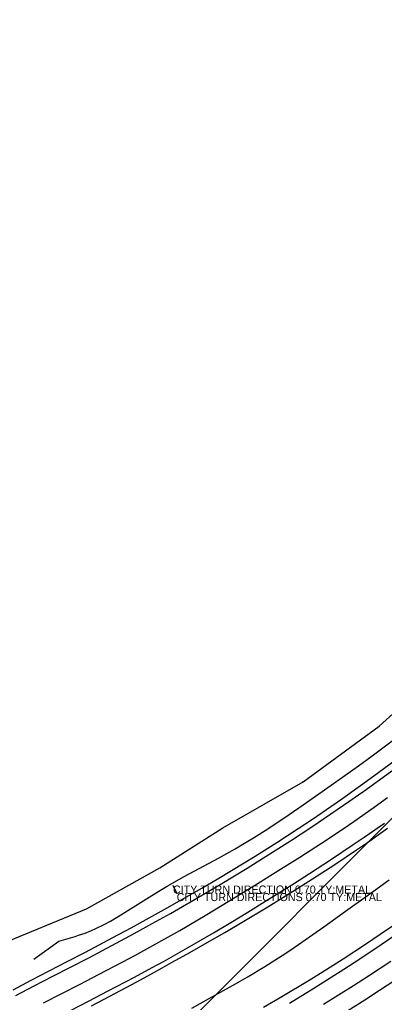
# Model space of a CAD drawing. Extents: x 1676038 to 1677961, y 226475 to 233854.
# Drawn here: x 1676549 to 1676777, y 227687 to 228301 of the extents above; entities that cross this region are included whole.
import ezdxf

# ---------------------------------------------------------------- set-up
doc = ezdxf.new("R2010")
doc.units = 0
for name, color, linetype in [('S_BASELINE', 7, 'Continuous'), ('S_DITCHLINE', 7, 'Continuous'), ('S_EDGE_PAVEMENT', 7, 'Continuous'), ('S_FIBER_OPTIC_CABLE', 7, 'Continuous'), ('S_MSC_PT_SYM', 7, 'Continuous'), ('S_PAVEMENT_CROWN', 7, 'Continuous'), ('S_SHOULDER', 7, 'Continuous'), ('S_SIGN', 7, 'Continuous'), ('S_SIGN_ANNOT', 7, 'Continuous'), ('S_UTL_PT_SYM', 7, 'Continuous')]:
    doc.layers.add(name, color=color, linetype=linetype)

msp = doc.modelspace()

# ---------------------------------------------------------------- linework, layer by layer
at = {"layer": 'S_BASELINE'}
msp.add_line((1676625.89, 227646.73), (1677368.16, 228389.18), dxfattribs=at)
at = {"layer": 'S_DITCHLINE'}
for points in [[(1676557.64, 227714.12), (1676573.09, 227725.4), (1676583.33, 227728.42), (1676585.43, 227729.06), (1676589.57, 227730.51), (1676593.62, 227732.15), (1676596.28, 227733.34), (1676601.53, 227735.92), (1676605.4, 227738), (1676613.02, 227742.46), (1676628.03, 227751.95), (1676635.56, 227756.66), (1676640.82, 227759.78), (1676651.43, 227765.74), (1676672.81, 227777.22), (1676683.4, 227783.11), (1676690.27, 227787.16), (1676694.8, 227789.93), (1676703.79, 227795.62), (1676717.1, 227804.49), (1676725.88, 227810.55), (1676743.33, 227822.85), (1676760.37, 227834.97), (1676768.81, 227841.12), (1676781.31, 227850.55)], [(1676656.22, 227683.66), (1676668.56, 227690.37), (1676683.49, 227698.72), (1676690.87, 227703.03), (1676701.83, 227709.66), (1676712.65, 227716.51), (1676718, 227720.02), (1676724.96, 227724.71), (1676738.72, 227734.32), (1676752.33, 227744.15), (1676765.94, 227753.99), (1676779.59, 227763.79)]]:
    msp.add_lwpolyline(points, dxfattribs=at)
at = {"layer": 'S_EDGE_PAVEMENT'}
for points in [[(1676546.31, 227691.55), (1676557.7, 227697.44), (1676569.08, 227703.32), (1676580.47, 227709.21), (1676591.86, 227715.09), (1676608.97, 227724.09), (1676620.31, 227730.21), (1676631.57, 227736.48), (1676642.83, 227742.74), (1676664.28, 227755.12), (1676674.93, 227761.44), (1676690.82, 227771.09), (1676708.87, 227782.39), (1676717.84, 227788.15), (1676731.2, 227796.91), (1676751.05, 227810.35), (1676763.67, 227819.17), (1676772.03, 227825.14), (1676788.62, 227837.24)], [(1676580.56, 227682.15), (1676592.12, 227688.13), (1676603.67, 227694.11), (1676620.43, 227702.92), (1676631.53, 227708.93), (1676638.9, 227713), (1676653.56, 227721.26), (1676669.8, 227730.7), (1676680.55, 227737.1), (1676691.25, 227743.62), (1676701.94, 227750.13), (1676720.46, 227761.74), (1676729.67, 227767.63), (1676743.4, 227776.59), (1676757.03, 227785.7), (1676763.8, 227790.32), (1676776.54, 227799.18)], [(1676717.25, 227686.68), (1676732.39, 227696.01), (1676751.22, 227707.95), (1676760.57, 227714.03), (1676774.51, 227723.28), (1676788.32, 227732.7)], [(1676745.7, 227677.12), (1676764.28, 227688.81), (1676773.52, 227694.75), (1676787.29, 227703.77)]]:
    msp.add_lwpolyline(points, dxfattribs=at)
at = {"layer": 'S_FIBER_OPTIC_CABLE'}
for p, q in [((1676773.26, 227859.62), (1676816.44, 227899.08)), ((1676725.71, 227825.01), (1676773.26, 227859.62)), ((1676675.62, 227796.16), (1676725.71, 227825.01)), ((1676636.29, 227771.17), (1676675.62, 227796.16)), ((1676590.51, 227745.62), (1676636.29, 227771.17)), ((1676524.86, 227718.7), (1676590.51, 227745.62))]:
    msp.add_line(p, q, dxfattribs=at)
at = {"layer": 'S_MSC_PT_SYM'}
for points in [[(1676644.47, 227760.17), (1676644.47, 227760.22), (1676644.47, 227760.17), (1676644.42, 227760.17), (1676644.47, 227760.17), (1676644.47, 227760.12), (1676644.47, 227760.17), (1676644.52, 227760.17)], [(1676646.79, 227755.44), (1676646.79, 227755.49), (1676646.79, 227755.44), (1676646.74, 227755.44), (1676646.79, 227755.44), (1676646.79, 227755.39), (1676646.79, 227755.44), (1676646.84, 227755.44)]]:
    msp.add_lwpolyline(points, dxfattribs=at)
at = {"layer": 'S_PAVEMENT_CROWN'}
for points in [[(1676563.62, 227686.84), (1676575.04, 227692.73), (1676586.46, 227698.63), (1676597.89, 227704.52), (1676613.1, 227712.47), (1676620.67, 227716.52), (1676631.97, 227722.67), (1676648.78, 227732.15), (1676664.65, 227741.49), (1676675.16, 227747.83), (1676696.09, 227760.67), (1676709.88, 227769.24), (1676723.67, 227777.8), (1676737.33, 227786.55), (1676750.85, 227795.53), (1676757.53, 227800.12), (1676770.18, 227809.13), (1676778.53, 227815.24)], [(1676738.42, 227685.98), (1676757.29, 227697.82), (1676766.67, 227703.83), (1676780.65, 227712.98)]]:
    msp.add_lwpolyline(points, dxfattribs=at)
at = {"layer": 'S_SHOULDER'}
for points in [[(1676544.58, 227695.11), (1676555.87, 227700.98), (1676567.16, 227706.86), (1676578.45, 227712.73), (1676589.74, 227718.6), (1676606.9, 227727.65), (1676618.29, 227733.77), (1676629.61, 227740.01), (1676640.94, 227746.25), (1676662.45, 227758.48), (1676673.13, 227764.72), (1676689.03, 227774.29), (1676695.82, 227778.48), (1676709.31, 227787.01), (1676722.68, 227795.72), (1676731.53, 227801.63), (1676749.06, 227813.67), (1676761.63, 227822.56), (1676769.95, 227828.57), (1676786.46, 227840.75)], [(1676593.67, 227684.93), (1676605.09, 227690.97), (1676621.82, 227699.95), (1676632.91, 227706.04), (1676643.95, 227712.24), (1676654.99, 227718.43), (1676665.88, 227724.68), (1676676.77, 227730.93), (1676687.6, 227737.28), (1676703.77, 227746.93), (1676722.45, 227758.42), (1676731.71, 227764.27), (1676745.51, 227773.22), (1676759.16, 227782.38), (1676765.93, 227787.04), (1676778.55, 227795.98)], [(1676700.95, 227684.2), (1676712.44, 227690.88), (1676729.54, 227701.1), (1676736.64, 227705.48), (1676750.74, 227714.42), (1676764.71, 227723.57), (1676773.96, 227729.76), (1676792.33, 227742.34)]]:
    msp.add_lwpolyline(points, dxfattribs=at)
at = {"layer": 'S_SIGN'}
msp.add_line((1676644.47, 227760.17), (1676646.79, 227755.44), dxfattribs=at)
at = {"layer": 'S_UTL_PT_SYM'}
for points in [[(1676773.26, 227859.62), (1676773.26, 227859.67), (1676773.26, 227859.62), (1676773.21, 227859.62), (1676773.26, 227859.62), (1676773.26, 227859.57), (1676773.26, 227859.62), (1676773.31, 227859.62)], [(1676725.71, 227825.01), (1676725.71, 227825.06), (1676725.71, 227825.01), (1676725.66, 227825.01), (1676725.71, 227825.01), (1676725.71, 227824.96), (1676725.71, 227825.01), (1676725.76, 227825.01)], [(1676675.62, 227796.16), (1676675.62, 227796.21), (1676675.62, 227796.16), (1676675.57, 227796.16), (1676675.62, 227796.16), (1676675.62, 227796.11), (1676675.62, 227796.16), (1676675.67, 227796.16)], [(1676636.29, 227771.17), (1676636.29, 227771.22), (1676636.29, 227771.17), (1676636.24, 227771.17), (1676636.29, 227771.17), (1676636.29, 227771.12), (1676636.29, 227771.17), (1676636.34, 227771.17)], [(1676590.51, 227745.62), (1676590.51, 227745.67), (1676590.51, 227745.62), (1676590.46, 227745.62), (1676590.51, 227745.62), (1676590.51, 227745.57), (1676590.51, 227745.62), (1676590.56, 227745.62)]]:
    msp.add_lwpolyline(points, dxfattribs=at)

# ---------------------------------------------------------------- texts
at = {"layer": 'S_SIGN_ANNOT'}
for s, p in [('CITY TURN DIRECTION 0.70 TY:METAL', (1676644.47, 227755.17)), ('CITY TURN DIRECTIONS 0.70 TY:METAL', (1676646.79, 227750.44))]:
    msp.add_text(s, height=5, dxfattribs=at).set_placement(p)

doc.saveas('drawing.dxf')
